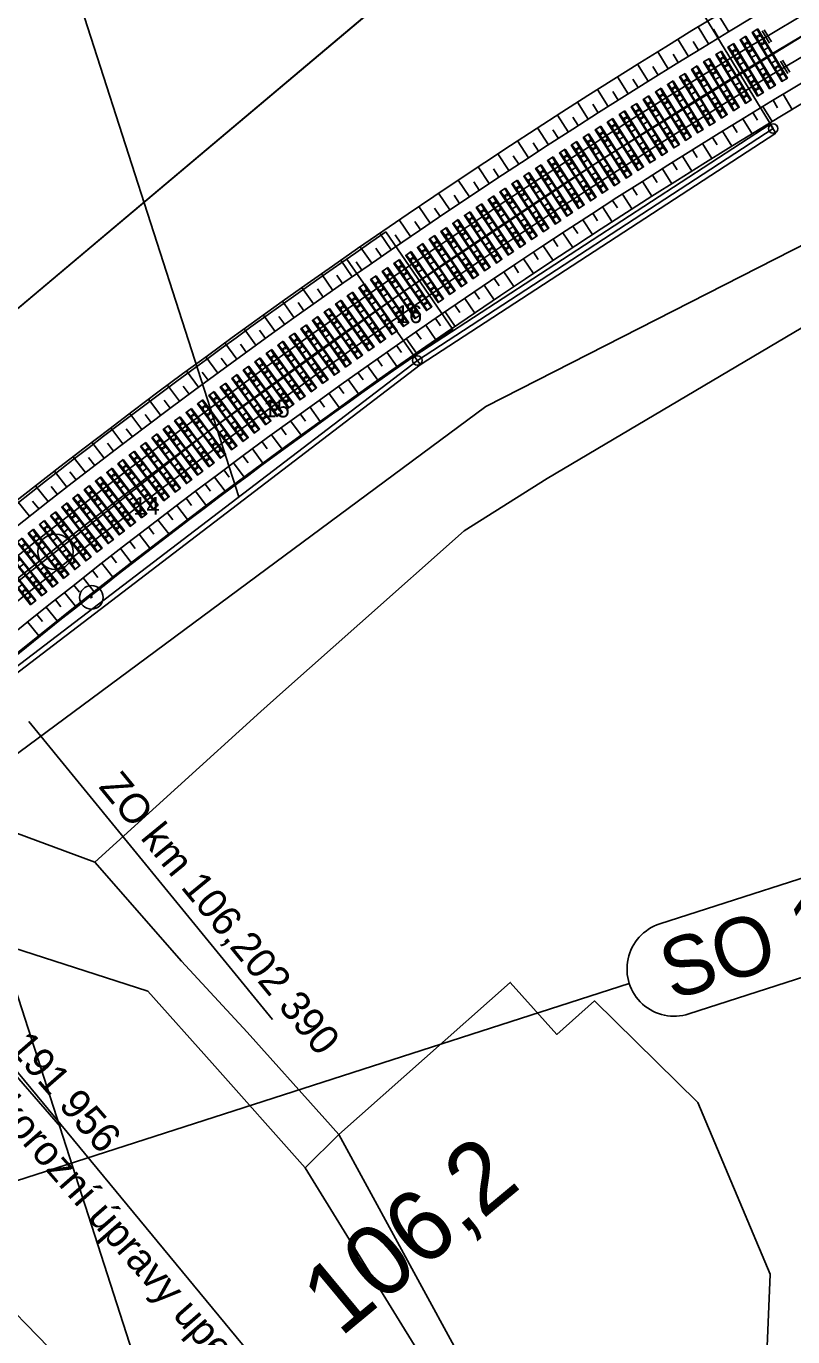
# Model space of a CAD drawing. Extents: x -758836 to -757729, y -1175316 to -1174366.
# Drawn here: x -758387.8 to -758355.4, y -1174861 to -1174805.6 of the extents above; entities that cross this region are included whole.
import ezdxf

# ---------------------------------------------------------------- set-up
doc = ezdxf.new("R2010")
doc.units = 0
for name, color, linetype in [('_NOR-návrh silná', 7, 'Continuous'), ('_NOR-návrh tenká', 7, 'Continuous'), ('_NOR-osa', 7, 'Continuous'), ('_NOR-pomocná', 7, 'Continuous'), ('_NOR-popis', 7, 'Continuous'), ('_NOR-pražce', 7, 'Continuous'), ('_NOR-sanace', 7, 'Continuous'), ('_NOR-svahy', 7, 'Continuous'), ('_NOR-vytyčení', 7, 'Continuous'), ('G_Obvod stavby', 7, 'Continuous'), ('Hranice parcel', 7, 'Continuous'), ('Vrstva 1', 7, 'Continuous'), ('Vrstva 7', 7, 'Continuous')]:
    doc.layers.add(name, color=color, linetype=linetype)

# ---------------------------------------------------------------- blocks, each defined once
blk = doc.blocks.new('C093_1')
at = {"layer": 'Vrstva 7'}
blk.add_line((-0.05, 0), (0.05, 0), dxfattribs=at)
blk.add_circle((0, 0), 0.5, dxfattribs=at)
blk = doc.blocks.new('C513_1')
at = {"layer": 'Vrstva 7'}
blk.add_circle((0, 0), 0.75, dxfattribs=at)
blk = doc.blocks.new('půdorys-SB8')
at = {"layer": '_NOR-pražce'}
for p, q in [((-1.21, 0.109), (-0.96, 0.095)), ((-0.96, 0.095), (-0.56, 0.099)), ((-0.96, 0.095), (-0.96, -0.095)), ((-0.56, 0.099), (-0.32, 0.109)), ((-0.56, 0.099), (-0.56, -0.1)), ((-0.32, 0.109), (0.32, 0.109)), ((-0.32, 0.109), (-0.32, -0.11)), ((0.56, 0.099), (0.32, 0.109)), ((0.32, -0.11), (0.32, 0.109)), ((0.96, 0.095), (0.56, 0.099)), ((0.56, 0.099), (0.56, -0.1)), ((1.21, 0.109), (0.96, 0.095)), ((0.96, 0.095), (0.96, -0.095)), ((-1.21, -0.11), (-0.96, -0.095)), ((-0.96, -0.095), (-0.56, -0.1)), ((-0.56, -0.1), (-0.32, -0.11)), ((-0.32, -0.11), (0.32, -0.11)), ((0.56, -0.1), (0.32, -0.11)), ((0.96, -0.095), (0.56, -0.1)), ((1.21, -0.11), (0.96, -0.095))]:
    blk.add_line(p, q, dxfattribs=at)
blk.add_lwpolyline([(-1.21, 0.142), (1.21, 0.142), (1.21, -0.142), (-1.21, -0.142)], close=True, dxfattribs=at)
for centre in [(-0.916, 0.048), (-0.604, 0.048), (0.604, 0.048), (0.916, 0.048), (-0.916, -0.048), (-0.604, -0.048), (0.604, -0.048), (0.916, -0.048)]:
    blk.add_circle(centre, 0.015, dxfattribs=at)
blk = doc.blocks.new('POINT_DISPLAY')
blk.add_line((0, 0), (0, 0))

msp = doc.modelspace()

# ---------------------------------------------------------------- linework, layer by layer
at = {"layer": '_NOR-návrh silná'}
for p, q in [((-758356.6, -1174805.702), (-758356.291, -1174806.216)), ((-758356.686, -1174805.753), (-758356.377, -1174806.268)), ((-758355.914, -1174807.04), (-758355.605, -1174807.554)), ((-758355.828, -1174806.988), (-758355.52, -1174807.503))]:
    msp.add_line(p, q, dxfattribs=at)
at = {"layer": '_NOR-návrh tenká'}
for p, q in [((-758356.223, -1174809.884), (-758360.288, -1174803.203)), ((-758356.34, -1174809.692), (-758371.395, -1174819.503)), ((-758371.266, -1174819.688), (-758356.223, -1174809.884)), ((-758356.106, -1174810.077), (-758371.14, -1174819.874)), ((-758356.34, -1174809.692), (-758356.106, -1174810.077)), ((-758371.395, -1174819.503), (-758371.138, -1174819.872)), ((-758391.422, -1174835.079), (-758371.266, -1174819.688)), ((-758391.278, -1174835.252), (-758371.14, -1174819.874))]:
    msp.add_line(p, q, dxfattribs=at)
for centre in [(-758356.223, -1174809.884), (-758371.266, -1174819.688)]:
    msp.add_circle(centre, 0.2, dxfattribs=at)
for radius, start, end in [(295.6, 97.09776, 129.28488), (294.75, 97.0979, 129.28474), (293.75, 97.09807, 120.96729), (292.25, 97.09832, 120.96729), (291.3, 97.09848, 129.28417), (290.55, 97.09861, 129.28404), (293.75, 120.96729, 129.28457), (292.25, 120.96729, 129.28432)]:
    msp.add_arc((-758205.34, -1175057.864), radius, start, end, dxfattribs=at)
at = {"layer": '_NOR-osa'}
msp.add_arc((-758205.34, -1175057.864), 293, 97.09819, 129.28445, dxfattribs=at)
at = {"layer": '_NOR-pomocná'}
for points in [[(-758417.595, -1174755.224), (-758317.652, -1174723.031), (-758272.123, -1174864.38), (-758372.066, -1174896.572)], [(-758517.538, -1174787.416), (-758417.595, -1174755.224), (-758372.066, -1174896.572), (-758472.009, -1174928.764)]]:
    msp.add_lwpolyline(points, close=True, dxfattribs=at)
at = {"layer": '_NOR-popis'}
for p, q in [((-758387.693, -1174834.949), (-758377.385, -1174847.55)), ((-758395.533, -1174841.585), (-758386.352, -1174852.094)), ((-758362.304, -1174846.032), (-758391.059, -1174855.295))]:
    msp.add_line(p, q, dxfattribs=at)
for points in [[(-758388.955, -1174762.992), (-758397.997, -1174765.904), (-758378.816, -1174825.453)], [(-758361.013, -1174843.516), (-758351.971, -1174840.603)], [(-758341.702, -1174841.498), (-758359.787, -1174847.323)]]:
    msp.add_lwpolyline(points, dxfattribs=at)
msp.add_arc((-758360.4, -1174845.419), 2, 107.8533, 287.854, dxfattribs=at)
at = {"layer": '_NOR-sanace'}
for p, q in [((-758369.764, -1174818.375), (-758372.594, -1174814.253)), ((-758371.395, -1174819.503), (-758374.253, -1174815.4))]:
    msp.add_line(p, q, dxfattribs=at)
for radius, end in [(295.5, 129.28486), (290.5, 129.28403)]:
    msp.add_arc((-758205.34, -1175057.864), radius, 124.47202, end, dxfattribs=at)
at = {"layer": '_NOR-svahy'}
for points in [[(-758358.097, -1174805.787), (-758358.538, -1174805.06)], [(-758358.952, -1174806.307), (-758359.395, -1174805.581)], [(-758358.525, -1174806.047), (-758358.745, -1174805.684)], [(-758359.804, -1174806.829), (-758360.25, -1174806.106)], [(-758359.378, -1174806.568), (-758359.6, -1174806.205)], [(-758360.655, -1174807.355), (-758361.103, -1174806.633)], [(-758360.23, -1174807.092), (-758360.453, -1174806.73)], [(-758361.504, -1174807.883), (-758361.954, -1174807.162)], [(-758361.08, -1174807.619), (-758361.304, -1174807.258)], [(-758362.351, -1174808.415), (-758362.804, -1174807.695)], [(-758361.928, -1174808.149), (-758362.154, -1174807.789)], [(-758363.197, -1174808.949), (-758363.652, -1174808.231)], [(-758362.774, -1174808.681), (-758363.001, -1174808.322)], [(-758355.797, -1174808.428), (-758355.41, -1174809.07)], [(-758364.04, -1174809.486), (-758364.498, -1174808.769)], [(-758363.619, -1174809.217), (-758363.847, -1174808.858)], [(-758356.653, -1174808.946), (-758356.263, -1174809.587)], [(-758356.225, -1174808.687), (-758356.031, -1174809.008)], [(-758364.882, -1174810.026), (-758365.342, -1174809.311)], [(-758364.461, -1174809.755), (-758364.691, -1174809.398)], [(-758357.506, -1174809.467), (-758357.114, -1174810.107)], [(-758357.08, -1174809.206), (-758356.884, -1174809.526)], [(-758365.722, -1174810.568), (-758366.184, -1174809.855)], [(-758365.302, -1174810.297), (-758365.533, -1174809.94)], [(-758358.358, -1174809.991), (-758357.964, -1174810.629)], [(-758357.932, -1174809.729), (-758357.736, -1174810.048)], [(-758366.56, -1174811.114), (-758367.025, -1174810.402)], [(-758366.141, -1174810.841), (-758366.373, -1174810.485)], [(-758359.208, -1174810.518), (-758358.812, -1174811.154)], [(-758358.783, -1174810.254), (-758358.586, -1174810.573)], [(-758367.396, -1174811.662), (-758367.863, -1174810.952)], [(-758366.978, -1174811.388), (-758367.211, -1174811.032)], [(-758360.056, -1174811.047), (-758359.658, -1174811.683)], [(-758359.632, -1174810.782), (-758359.434, -1174811.1)], [(-758368.23, -1174812.213), (-758368.7, -1174811.505)], [(-758367.814, -1174811.938), (-758368.048, -1174811.583)], [(-758360.903, -1174811.58), (-758360.502, -1174812.214)], [(-758360.48, -1174811.313), (-758360.28, -1174811.631)], [(-758369.063, -1174812.768), (-758369.535, -1174812.061)], [(-758368.647, -1174812.49), (-758368.882, -1174812.136)], [(-758361.747, -1174812.115), (-758361.345, -1174812.748)], [(-758361.325, -1174811.847), (-758361.124, -1174812.164)], [(-758369.894, -1174813.324), (-758370.368, -1174812.619)], [(-758369.478, -1174813.046), (-758369.715, -1174812.693)], [(-758363.011, -1174812.924), (-758362.808, -1174813.239)], [(-758362.59, -1174812.654), (-758362.185, -1174813.285)], [(-758362.169, -1174812.384), (-758361.967, -1174812.7)], [(-758370.722, -1174813.884), (-758371.199, -1174813.18)], [(-758370.308, -1174813.604), (-758370.546, -1174813.252)], [(-758363.85, -1174813.467), (-758363.646, -1174813.781)], [(-758363.431, -1174813.195), (-758363.024, -1174813.825)], [(-758371.549, -1174814.447), (-758372.028, -1174813.745)], [(-758371.136, -1174814.165), (-758371.375, -1174813.814)], [(-758364.689, -1174814.012), (-758364.483, -1174814.326)], [(-758364.27, -1174813.739), (-758363.861, -1174814.368)], [(-758372.374, -1174815.012), (-758372.856, -1174814.312)], [(-758371.962, -1174814.729), (-758372.202, -1174814.378)], [(-758365.525, -1174814.561), (-758365.319, -1174814.874)], [(-758365.107, -1174814.286), (-758364.696, -1174814.913)], [(-758373.197, -1174815.58), (-758373.681, -1174814.881)], [(-758372.786, -1174815.296), (-758373.027, -1174814.946)], [(-758366.359, -1174815.112), (-758366.152, -1174815.425)], [(-758365.942, -1174814.836), (-758365.529, -1174815.462)], [(-758374.018, -1174816.151), (-758374.504, -1174815.454)], [(-758373.608, -1174815.865), (-758373.85, -1174815.516)], [(-758367.191, -1174815.666), (-758366.983, -1174815.978)], [(-758366.775, -1174815.389), (-758366.36, -1174816.013)], [(-758374.837, -1174816.725), (-758375.326, -1174816.029)], [(-758374.428, -1174816.437), (-758374.672, -1174816.089)], [(-758368.022, -1174816.223), (-758367.812, -1174816.534)], [(-758367.607, -1174815.944), (-758367.189, -1174816.567)], [(-758375.654, -1174817.301), (-758376.145, -1174816.607)], [(-758375.246, -1174817.012), (-758375.491, -1174816.665)], [(-758368.85, -1174816.783), (-758368.64, -1174817.094)], [(-758368.436, -1174816.503), (-758368.016, -1174817.124)], [(-758376.469, -1174817.88), (-758376.963, -1174817.188)], [(-758376.062, -1174817.59), (-758376.308, -1174817.244)], [(-758369.677, -1174817.346), (-758369.466, -1174817.656)], [(-758369.264, -1174817.064), (-758368.842, -1174817.684)], [(-758377.283, -1174818.462), (-758377.778, -1174817.772)], [(-758376.876, -1174818.171), (-758377.124, -1174817.825)], [(-758370.502, -1174817.911), (-758370.289, -1174818.22)], [(-758370.09, -1174817.628), (-758369.665, -1174818.247)], [(-758378.094, -1174819.047), (-758378.592, -1174818.358)], [(-758377.688, -1174818.754), (-758377.937, -1174818.409)], [(-758370.913, -1174818.195), (-758370.487, -1174818.812)], [(-758378.903, -1174819.634), (-758379.404, -1174818.947)], [(-758378.499, -1174819.34), (-758378.748, -1174818.996)], [(-758371.735, -1174818.765), (-758371.307, -1174819.381)], [(-758371.325, -1174818.48), (-758371.111, -1174818.788)], [(-758379.71, -1174820.225), (-758380.213, -1174819.539)], [(-758379.307, -1174819.929), (-758379.558, -1174819.586)], [(-758372.555, -1174819.338), (-758372.124, -1174819.952)], [(-758372.145, -1174819.051), (-758371.931, -1174819.359)], [(-758380.515, -1174820.818), (-758381.021, -1174820.134)], [(-758373.373, -1174819.913), (-758372.94, -1174820.526)], [(-758372.964, -1174819.625), (-758372.748, -1174819.932)], [(-758380.113, -1174820.521), (-758380.365, -1174820.178)], [(-758374.189, -1174820.491), (-758373.754, -1174821.103)], [(-758373.781, -1174820.202), (-758373.564, -1174820.508)], [(-758381.319, -1174821.413), (-758381.826, -1174820.731)], [(-758380.917, -1174821.115), (-758381.171, -1174820.774)], [(-758375.003, -1174821.072), (-758374.566, -1174821.682)], [(-758374.596, -1174820.782), (-758374.378, -1174821.087)], [(-758382.12, -1174822.012), (-758382.63, -1174821.331)], [(-758381.72, -1174821.712), (-758381.974, -1174821.372)], [(-758375.814, -1174821.656), (-758375.376, -1174822.264)], [(-758375.409, -1174821.364), (-758375.19, -1174821.668)], [(-758382.919, -1174822.613), (-758383.431, -1174821.934)], [(-758382.52, -1174822.312), (-758382.775, -1174821.972)], [(-758376.624, -1174822.243), (-758376.183, -1174822.85)], [(-758376.22, -1174821.949), (-758376, -1174822.253)], [(-758383.716, -1174823.217), (-758384.231, -1174822.54)], [(-758383.318, -1174822.914), (-758383.575, -1174822.576)], [(-758377.432, -1174822.832), (-758376.989, -1174823.437)], [(-758377.029, -1174822.537), (-758376.807, -1174822.84)], [(-758384.511, -1174823.823), (-758385.028, -1174823.148)], [(-758384.114, -1174823.519), (-758384.372, -1174823.182)], [(-758378.238, -1174823.424), (-758377.793, -1174824.028)], [(-758377.835, -1174823.128), (-758377.613, -1174823.43)], [(-758385.304, -1174824.432), (-758385.823, -1174823.759)], [(-758384.908, -1174824.127), (-758385.167, -1174823.79)], [(-758379.042, -1174824.019), (-758378.595, -1174824.621)], [(-758378.64, -1174823.722), (-758378.417, -1174824.023)], [(-758386.095, -1174825.044), (-758386.616, -1174824.373)], [(-758385.7, -1174824.738), (-758385.96, -1174824.402)], [(-758379.443, -1174824.318), (-758379.219, -1174824.619)], [(-758386.884, -1174825.659), (-758387.408, -1174824.989)], [(-758386.49, -1174825.351), (-758386.751, -1174825.016)], [(-758380.244, -1174824.917), (-758380.018, -1174825.217)], [(-758379.844, -1174824.617), (-758379.394, -1174825.218)], [(-758387.671, -1174826.276), (-758388.197, -1174825.608)], [(-758387.278, -1174825.967), (-758387.54, -1174825.633)], [(-758381.042, -1174825.519), (-758380.816, -1174825.818)], [(-758380.643, -1174825.217), (-758380.192, -1174825.816)], [(-758381.839, -1174826.123), (-758381.612, -1174826.422)], [(-758381.441, -1174825.821), (-758380.987, -1174826.418)], [(-758382.633, -1174826.731), (-758382.405, -1174827.028)], [(-758382.236, -1174826.427), (-758381.781, -1174827.022)], [(-758383.426, -1174827.341), (-758383.197, -1174827.637)], [(-758383.03, -1174827.035), (-758382.572, -1174827.629)], [(-758383.821, -1174827.647), (-758383.362, -1174828.239)], [(-758384.61, -1174828.261), (-758384.149, -1174828.852)], [(-758384.216, -1174827.953), (-758383.986, -1174828.249)], [(-758385.398, -1174828.877), (-758384.934, -1174829.467)], [(-758385.004, -1174828.569), (-758384.773, -1174828.864)], [(-758386.183, -1174829.497), (-758385.717, -1174830.085)], [(-758385.79, -1174829.187), (-758385.558, -1174829.481)], [(-758386.574, -1174829.808), (-758386.341, -1174830.101)], [(-758387.356, -1174830.431), (-758387.122, -1174830.724)], [(-758386.965, -1174830.119), (-758386.498, -1174830.705)], [(-758387.746, -1174830.744), (-758387.277, -1174831.329)]]:
    msp.add_lwpolyline(points, dxfattribs=at)
at = {"layer": 'G_Obvod stavby'}
msp.add_lwpolyline([(-758392.72, -1174840.756), (-758391.23, -1174838.56), (-758368.37, -1174821.64), (-758340.31, -1174807.33), (-758320.27, -1174796.89), (-758301, -1174790.21), (-758267.96, -1174782.93), (-758224.96, -1174775.27), (-758184.87, -1174772.83), (-758142.71, -1174770.26), (-758089.84, -1174768.68), (-758106.02, -1174731.44), (-758149.09, -1174725.67), (-758199.62, -1174726.6), (-758225.76, -1174732.36), (-758252.17, -1174738.18), (-758254.97, -1174739.34), (-758266.58, -1174744.16), (-758279.45, -1174749.49), (-758302.42, -1174759.02), (-758331.68, -1174770.24), (-758367.17, -1174799.81), (-758405.64, -1174832.2)], dxfattribs=at)
at = {"layer": 'Hranice parcel'}
for p, q in [((-758405.64, -1174832.2), (-758367.17, -1174799.81)), ((-758384.91, -1174840.91), (-758391.23, -1174838.56)), ((-758376.01, -1174853.83), (-758374.59, -1174852.42)), ((-758376.01, -1174853.83), (-758364.48, -1174872.56))]:
    msp.add_line(p, q, dxfattribs=at)
for points in [[(-758340.31, -1174807.33), (-758368.37, -1174821.64), (-758391.23, -1174838.56)], [(-758352.89, -1174817.05), (-758365.77, -1174824.68), (-758369.29, -1174826.9), (-758373.7, -1174830.81), (-758376.95, -1174833.7), (-758377.89, -1174834.53), (-758384.91, -1174840.91)], [(-758384.91, -1174840.91), (-758381.24, -1174845.09), (-758378.46, -1174848.09), (-758375.18, -1174851.76), (-758374.59, -1174852.42)], [(-758394.04, -1174842.7), (-758386.64, -1174845.08), (-758382.66, -1174846.36), (-758379.94, -1174849.4), (-758376.01, -1174853.83)], [(-758394.04, -1174842.7), (-758378.39, -1174861.63), (-758372.47, -1174875.16), (-758371.87, -1174876.54), (-758365.08, -1174901.85)], [(-758374.59, -1174852.42), (-758367.34, -1174845.99), (-758365.37, -1174848.19), (-758363.78, -1174846.77), (-758359.4, -1174851.07), (-758356.35, -1174858.32), (-758356.78, -1174868.83)], [(-758374.59, -1174852.42), (-758363.8, -1174872.21), (-758362.51, -1174871.59)], [(-758365.08, -1174901.85), (-758366.5, -1174900.55), (-758372.65, -1174883.97), (-758377.61, -1174873.09), (-758384.95, -1174863.38), (-758391.15, -1174857.01)]]:
    msp.add_lwpolyline(points, dxfattribs=at)
at = {"layer": 'Vrstva 1'}
msp.add_lwpolyline([(-758443.817, -1174881.252), (-758441.673, -1174879.1), (-758423.412, -1174860.854), (-758412.446, -1174850.23), (-758405.322, -1174843.614), (-758399.028, -1174837.996), (-758392.64, -1174832.554), (-758380.106, -1174822.693), (-758371.773, -1174816.721), (-758363.37, -1174811.125), (-758354.46, -1174805.649), (-758345.526, -1174800.592), (-758336.614, -1174795.909), (-758327.338, -1174791.462), (-758317.813, -1174787.314), (-758307.666, -1174783.315), (-758298.059, -1174779.921), (-758285.017, -1174775.914), (-758275.047, -1174773.289)], dxfattribs=at)

# ---------------------------------------------------------------- block references
at = {"layer": '_NOR-pražce'}
for p, rotation in [((-758356.359, -1174806.782), -58.974233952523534), ((-758356.872, -1174807.091), -58.85720429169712), ((-758357.895, -1174807.712), -58.623144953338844), ((-758357.383, -1174807.401), -58.74017459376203), ((-758358.915, -1174808.337), -58.38908558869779), ((-758358.405, -1174808.024), -58.506115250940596), ((-758359.933, -1174808.967), -58.155026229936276), ((-758359.425, -1174808.652), -58.27205592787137), ((-758360.949, -1174809.6), -57.920966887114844), ((-758360.441, -1174809.283), -58.03799658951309), ((-758361.456, -1174809.919), -57.80393722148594), ((-758362.467, -1174810.559), -57.56987785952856), ((-758361.962, -1174810.238), -57.6869075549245), ((-758363.476, -1174811.203), -57.33581850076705), ((-758362.972, -1174810.88), -57.45284819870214), ((-758363.98, -1174811.526), -57.218788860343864), ((-758364.985, -1174812.176), -56.98472949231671), ((-758364.483, -1174811.851), -57.101759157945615), ((-758365.987, -1174812.83), -56.75067012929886), ((-758365.486, -1174812.503), -56.86769982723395), ((-758366.487, -1174813.159), -56.63364048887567), ((-758367.485, -1174813.819), -56.399581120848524), ((-758366.987, -1174813.489), -56.51661078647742), ((-758368.481, -1174814.484), -56.1655217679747), ((-758367.984, -1174814.151), -56.28255145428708), ((-758368.978, -1174814.818), -56.048492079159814), ((-758369.969, -1174815.488), -55.814432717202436), ((-758369.474, -1174815.152), -55.93146241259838), ((-758370.958, -1174816.163), -55.58037335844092), ((-758370.464, -1174815.825), -55.69740305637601), ((-758371.451, -1174816.501), -55.46334371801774), ((-758372.436, -1174817.182), -55.229284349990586), ((-758371.944, -1174816.841), -55.34631401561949), ((-758373.418, -1174817.867), -54.99522498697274), ((-758372.927, -1174817.524), -55.112254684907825), ((-758373.908, -1174818.21), -54.878195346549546), ((-758374.885, -1174818.901), -54.64413597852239), ((-758374.397, -1174818.555), -54.76116564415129), ((-758375.373, -1174819.248), -54.52710631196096), ((-758376.346, -1174819.944), -54.29304696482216), ((-758375.86, -1174819.596), -54.41007662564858), ((-758377.317, -1174820.645), -54.05898762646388), ((-758376.832, -1174820.294), -54.17601726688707), ((-758377.801, -1174820.997), -53.941957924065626), ((-758378.767, -1174821.703), -53.70789860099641), ((-758378.285, -1174821.349), -53.82492826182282), ((-758379.249, -1174822.058), -53.59086890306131), ((-758380.211, -1174822.77), -53.356809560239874), ((-758379.731, -1174822.414), -53.47383926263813), ((-758380.691, -1174823.128), -53.239779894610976), ((-758381.648, -1174823.846), -53.0057205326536), ((-758381.17, -1174823.487), -53.12275022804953), ((-758382.126, -1174824.207), -52.88869087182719), ((-758383.079, -1174824.931), -52.6546315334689), ((-758382.603, -1174824.569), -52.771661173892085), ((-758383.554, -1174825.295), -52.53760183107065), ((-758384.503, -1174826.025), -52.303542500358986), ((-758384.029, -1174825.659), -52.42057216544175), ((-758384.976, -1174826.391), -52.18651280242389), ((-758385.92, -1174827.127), -51.95245345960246), ((-758385.449, -1174826.758), -52.06948316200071), ((-758386.391, -1174827.496), -51.83542379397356), ((-758387.331, -1174828.238), -51.60136444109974), ((-758386.861, -1174827.866), -51.71839412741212), ((-758387.799, -1174828.61), -51.48433478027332), ((-758388.267, -1174828.983), -51.36730508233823)]:
    msp.add_blockref('půdorys-SB8', p, dxfattribs=dict(at, rotation=rotation))
at = {"layer": '_NOR-vytyčení'}
for p in [(-758372.476, -1174817.21), (-758378.076, -1174821.197), (-758383.58, -1174825.314)]:
    msp.add_blockref('POINT_DISPLAY', p, dxfattribs=at)
at = {"layer": 'Vrstva 7', "rotation": 38.193547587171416}
for name, p in [('C513_1', (-758386.57, -1174827.778)), ('C093_1', (-758385.049, -1174829.708))]:
    msp.add_blockref(name, p, dxfattribs=at)

# ---------------------------------------------------------------- texts
at = {"layer": '_NOR-popis'}
for s, height, rotation, p in [('ZO km 106,202 390', 1.25, 309.2844, (-758384.773, -1174837.728)), ('SO 11-13-01', 2.5, 17.854, (-758360.489, -1174846.761)), ('km 106,191 956', 1.25, 311.1419, (-758392.525, -1174844.268)), ('konec antikorozní úpravy upevňovadel', 1.25, 311.1419, (-758394.182, -1174845.716)), ('106,2', 3, 39.7421, (-758374.521, -1174861.028)), ('začátek antikorozní úpravy upevňovadel', 1.25, 312.9634, (-758403.709, -1174854.398))]:
    msp.add_text(s, height=height, rotation=rotation, dxfattribs=at).set_placement(p)
at = {"layer": '_NOR-vytyčení'}
for s, p in [('16', (-758372.176, -1174818.11)), ('15', (-758377.776, -1174822.097)), ('14', (-758383.28, -1174826.214))]:
    msp.add_text(s, height=0.75, rotation=360, dxfattribs=at).set_placement(p)

doc.saveas('drawing.dxf')
